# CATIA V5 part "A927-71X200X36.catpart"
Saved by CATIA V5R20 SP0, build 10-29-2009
Part number: A927-71X200X36
Source: Unknown
Property "A": "36.000"
Property "ARTICLENO": "A927-71X200X36"
Property "BOMINFO": "A927-71X200X36"
Property "CODE": "A927-71X200X36"
Property "CREATOR": "CADENAS GmbH"
Property "D": "14.000"
Property "D1": "20.000"
Property "F": "18.000"
Property "FORM": "A"
Property "L": "200.000"
Property "L1": "90.000"
Property "L2": "20.000"
Property "L3": "50.000"
Property "LINA": "A927-71X200X36"
Property "NB": "A927-71X200X36"
Property "NBSYN": "$CODE."
Property "NN": "A927"
Property "NT": "VDI 3387 Removable Die Heels, steel and self-lubricating"
Property "R": "16.000"
Property "S": "36.000"
Property "SUPPLIER": "CF"
Property "T": "16.000"
Property "W": "71.000"
Bounding box of the stored display mesh (mm): x -35.5 to 35.5, y 0 to 200, z -36 to 0
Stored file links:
  C:\Users\borellobunino\Desktop\3D X SITO CF\A927\GSB_OILLESS_G2290507120036\CATIAV5\A927-71X200X36.catpart
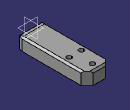
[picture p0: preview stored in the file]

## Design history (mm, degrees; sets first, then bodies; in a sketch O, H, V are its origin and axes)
Body1 "Geometry.1" (main body)
  Solid1 "A927-71X200X36.catpart": solid without history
